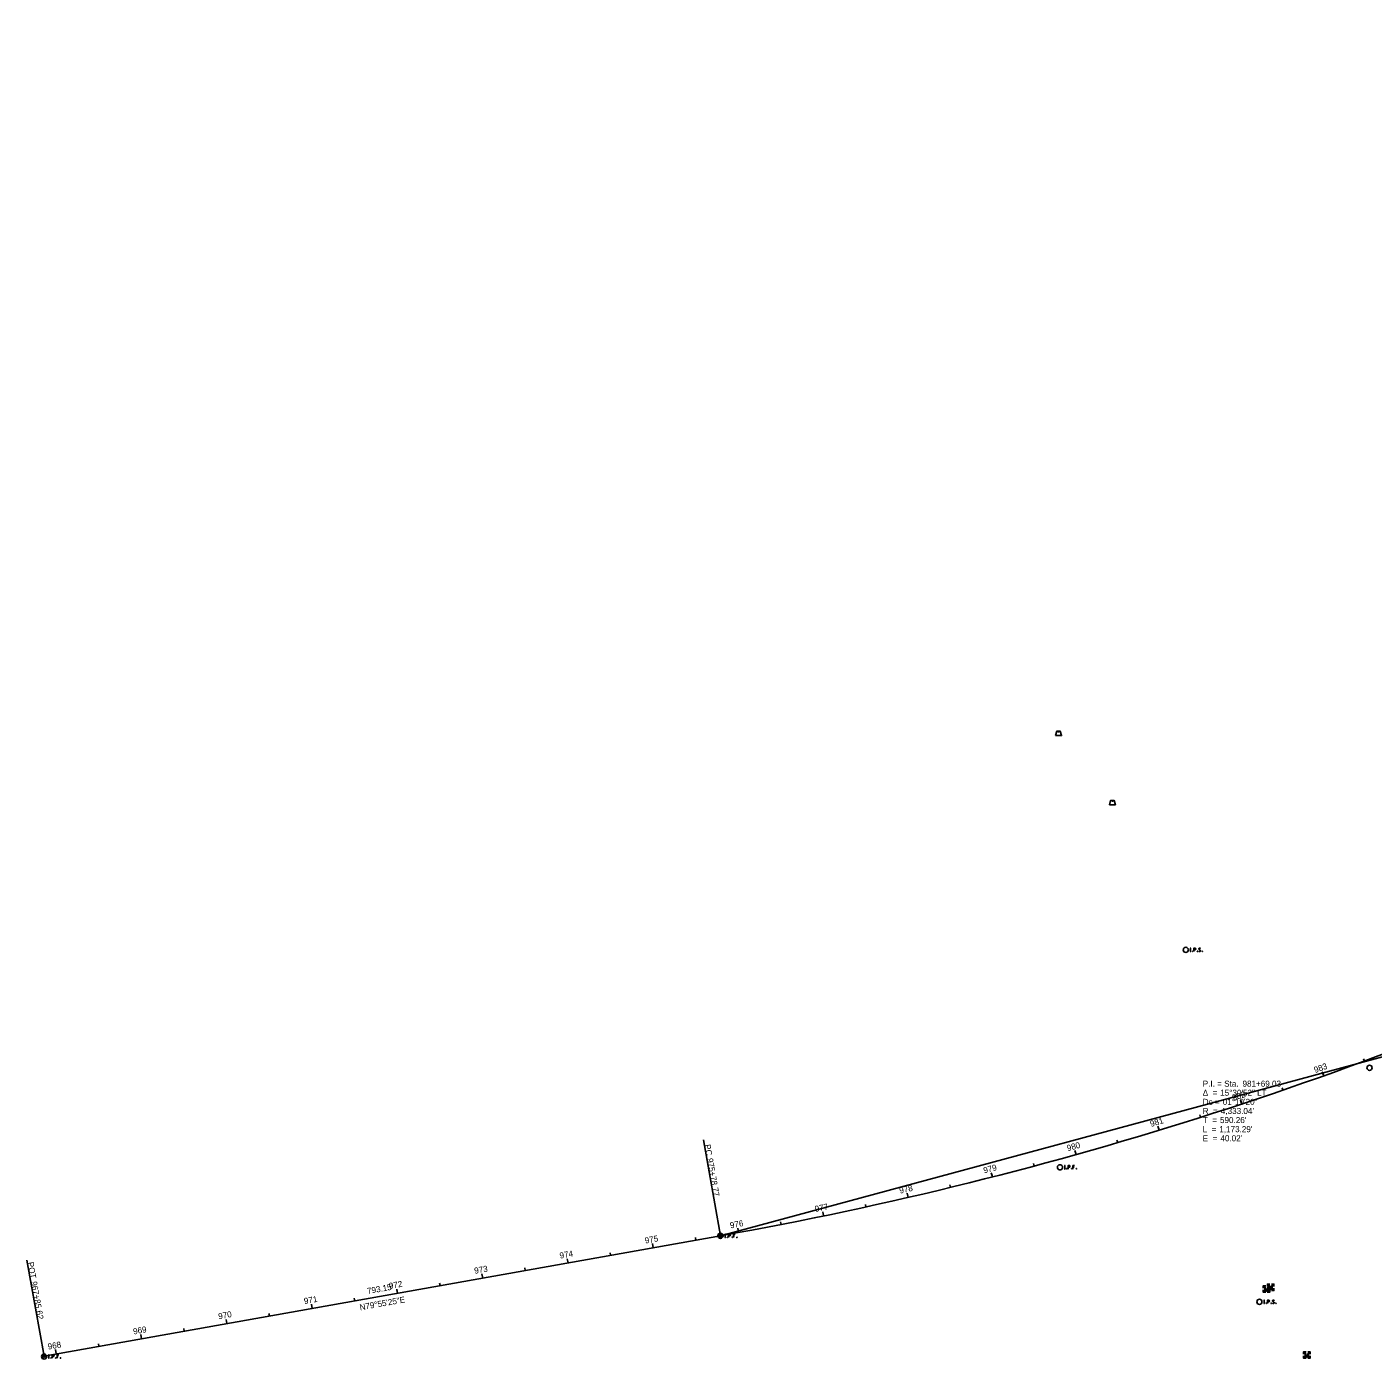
# Model space of a CAD drawing. Extents: x 2192033 to 2198234, y 657975 to 662607.
# Drawn here: x 2192033 to 2193587, y 660215 to 661753 of the extents above; entities that cross this region are included whole.
import ezdxf

# ---------------------------------------------------------------- set-up
doc = ezdxf.new("R2010")
doc.units = 0
for name, color, linetype in [('BR_P_Gen_Approach_Slab', 7, 'Continuous'), ('GE_X_Alignment_1000_Curve_Data', 7, 'Continuous'), ('GE_X_Alignment_1000_Stations', 7, 'Continuous'), ('GE_X_Alignment_100_Curve_Data', 7, 'Continuous'), ('GE_X_Alignment_100_Stations', 7, 'Continuous'), ('GE_X_Alignment_500_Curve_Data', 7, 'Continuous'), ('GE_X_Alignment_500_Stations', 7, 'Continuous'), ('RD_P_Text', 7, 'Continuous'), ('SH_Border', 7, 'Continuous'), ('SH_Named_Boundary', 7, 'Continuous')]:
    doc.layers.add(name, color=color, linetype=linetype)

msp = doc.modelspace()

# ---------------------------------------------------------------- linework, layer by layer
at = {"layer": 'BR_P_Gen_Approach_Slab'}
for points in [[(2193375.5, 660689.6), (2193376.4, 660689.6)], [(2193375.5, 660685.6), (2193376.4, 660685.6)], [(2193376, 660685.6), (2193376, 660689.6)], [(2193378.4, 660686.2), (2193378.5, 660686.2), (2193378.6, 660686.1), (2193378.7, 660686), (2193378.7, 660685.8), (2193378.6, 660685.7), (2193378.5, 660685.6), (2193378.4, 660685.6), (2193378.3, 660685.7), (2193378.2, 660685.8), (2193378.2, 660686), (2193378.3, 660686.1), (2193378.4, 660686.2)], [(2193379.9, 660685.6), (2193379.9, 660689.6), (2193381.2, 660689.6), (2193381.4, 660689.6), (2193381.6, 660689.5), (2193381.6, 660689.5), (2193381.7, 660689.4), (2193381.8, 660689.3), (2193381.9, 660689.1), (2193382, 660688.9), (2193382, 660688.5), (2193381.9, 660688.3), (2193381.9, 660688.2), (2193381.8, 660687.9), (2193381.7, 660687.8), (2193381.6, 660687.8), (2193381.4, 660687.7), (2193381.2, 660687.7), (2193379.9, 660687.7)], [(2193384, 660686.2), (2193384.1, 660686.2), (2193384.2, 660686.1), (2193384.3, 660686), (2193384.3, 660685.8), (2193384.2, 660685.7), (2193384.1, 660685.6), (2193384, 660685.6), (2193383.9, 660685.7), (2193383.8, 660685.8), (2193383.8, 660686), (2193383.9, 660686.1), (2193384, 660686.2)], [(2193387.4, 660689.4), (2193387.4, 660689.4), (2193387.3, 660689.5), (2193387, 660689.6), (2193386.7, 660689.6), (2193386.5, 660689.6), (2193386.4, 660689.6), (2193386.1, 660689.5), (2193385.8, 660689.4), (2193385.6, 660689.1), (2193385.5, 660688.9), (2193385.5, 660688.7), (2193385.6, 660688.4), (2193385.8, 660688.2), (2193387.3, 660687.2), (2193387.5, 660687.1), (2193387.5, 660687), (2193387.6, 660686.8), (2193387.6, 660686.6), (2193387.5, 660686.4), (2193387.5, 660686.3), (2193387.5, 660686.1), (2193387.4, 660686), (2193387.3, 660685.9), (2193387.3, 660685.8), (2193387.2, 660685.8), (2193387.1, 660685.7), (2193387, 660685.7), (2193386.7, 660685.6), (2193386.3, 660685.6), (2193386.1, 660685.7), (2193385.7, 660685.9), (2193385.5, 660686.1)], [(2193389.5, 660686.2), (2193389.6, 660686.2), (2193389.7, 660686.1), (2193389.8, 660686), (2193389.8, 660685.8), (2193389.7, 660685.7), (2193389.6, 660685.6), (2193389.5, 660685.6), (2193389.4, 660685.7), (2193389.3, 660685.8), (2193389.3, 660686), (2193389.4, 660686.1), (2193389.5, 660686.2)], [(2193460.6, 660283.4), (2193461.5, 660283.4)], [(2193460.6, 660279.4), (2193461.5, 660279.4)], [(2193461, 660279.4), (2193461, 660283.4)], [(2193463.4, 660279.9), (2193463.5, 660279.9), (2193463.6, 660279.9), (2193463.7, 660279.7), (2193463.7, 660279.6), (2193463.6, 660279.5), (2193463.5, 660279.4), (2193463.4, 660279.4), (2193463.3, 660279.5), (2193463.2, 660279.6), (2193463.2, 660279.7), (2193463.3, 660279.9), (2193463.4, 660279.9)], [(2193464.9, 660279.4), (2193464.9, 660283.4), (2193466.2, 660283.4), (2193466.4, 660283.4), (2193466.6, 660283.3), (2193466.7, 660283.2), (2193466.7, 660283.2), (2193466.9, 660283), (2193466.9, 660282.9), (2193467, 660282.6), (2193467, 660282.2), (2193467, 660282.1), (2193466.9, 660281.9), (2193466.8, 660281.7), (2193466.7, 660281.6), (2193466.6, 660281.5), (2193466.5, 660281.5), (2193466.2, 660281.4), (2193464.9, 660281.4)], [(2193469, 660279.9), (2193469.2, 660279.9), (2193469.3, 660279.9), (2193469.3, 660279.7), (2193469.3, 660279.6), (2193469.3, 660279.5), (2193469.2, 660279.4), (2193469, 660279.4), (2193468.9, 660279.5), (2193468.9, 660279.6), (2193468.9, 660279.7), (2193468.9, 660279.9), (2193469, 660279.9)], [(2193472.4, 660283.1), (2193472.4, 660283.2), (2193472.3, 660283.2), (2193472.1, 660283.3), (2193471.8, 660283.4), (2193471.5, 660283.4), (2193471.5, 660283.4), (2193471.1, 660283.3), (2193470.8, 660283.1), (2193470.6, 660282.9), (2193470.5, 660282.6), (2193470.5, 660282.4), (2193470.6, 660282.2), (2193470.8, 660282), (2193472.3, 660281), (2193472.5, 660280.9), (2193472.5, 660280.8), (2193472.6, 660280.6), (2193472.6, 660280.4), (2193472.6, 660280.2), (2193472.5, 660280.1), (2193472.5, 660279.9), (2193472.4, 660279.8), (2193472.4, 660279.7), (2193472.3, 660279.6), (2193472.2, 660279.5), (2193472.1, 660279.5), (2193472, 660279.4), (2193471.8, 660279.4), (2193471.4, 660279.4), (2193471.1, 660279.5), (2193470.8, 660279.7), (2193470.5, 660279.9)], [(2193474.5, 660279.9), (2193474.6, 660279.9), (2193474.7, 660279.9), (2193474.8, 660279.7), (2193474.8, 660279.6), (2193474.7, 660279.5), (2193474.6, 660279.4), (2193474.5, 660279.4), (2193474.4, 660279.5), (2193474.3, 660279.6), (2193474.3, 660279.7), (2193474.4, 660279.9), (2193474.5, 660279.9)]]:
    msp.add_lwpolyline(points, dxfattribs=at)
for centre in [(2193370.5, 660687.6), (2193455.5, 660281.4)]:
    msp.add_circle(centre, 3, dxfattribs=at)
at = {"layer": 'GE_X_Alignment_1000_Stations'}
for p, q in [((2192833.4, 660357.6), (2192813.7, 660468.4)), ((2193243.9, 660451.3), (2193242.5, 660456.1)), ((2192755.8, 660343.8), (2192755.3, 660346.8)), ((2192052.5, 660218.8), (2192032.8, 660329.6)), ((2192263.5, 660256.3), (2192262.7, 660261.2))]:
    msp.add_line(p, q, dxfattribs=at)
for centre in [(2192833.4, 660357.6), (2192052.5, 660218.8)]:
    msp.add_circle(centre, 1.5, dxfattribs=at)
at = {"layer": 'GE_X_Alignment_100_Stations'}
for p, q in [((2193576.7, 660559.2), (2193575.7, 660562)), ((2193529.7, 660542.2), (2193528, 660546.9)), ((2193482.5, 660525.6), (2193481.6, 660528.5)), ((2193435.1, 660509.7), (2193433.6, 660514.4)), ((2193387.6, 660494.3), (2193386.7, 660497.1)), ((2193339.8, 660479.4), (2193338.4, 660484.2)), ((2192833.4, 660357.6), (2192813.7, 660468.4)), ((2193291.9, 660465.1), (2193291.1, 660468)), ((2193243.9, 660451.3), (2193242.5, 660456.1)), ((2193195.6, 660438.1), (2193194.9, 660441)), ((2193098.8, 660413.4), (2193098.1, 660416.3)), ((2193147.3, 660425.5), (2193146, 660430.3)), ((2193050.1, 660401.8), (2193049, 660406.7)), ((2192952.4, 660380.5), (2192951.4, 660385.4)), ((2193001.3, 660390.9), (2193000.7, 660393.8)), ((2192903.4, 660370.6), (2192902.8, 660373.6)), ((2192805, 660352.6), (2192804.5, 660355.5)), ((2192854.3, 660361.4), (2192853.4, 660366.3)), ((2192706.6, 660335.1), (2192706.1, 660338)), ((2192755.8, 660343.8), (2192754.9, 660348.7)), ((2192052.5, 660218.8), (2192032.8, 660329.6)), ((2192657.4, 660326.3), (2192656.5, 660331.2)), ((2192558.9, 660308.8), (2192558, 660313.7)), ((2192608.1, 660317.6), (2192607.6, 660320.5)), ((2192460.4, 660291.3), (2192459.6, 660296.2)), ((2192509.7, 660300.1), (2192509.1, 660303)), ((2192362, 660273.8), (2192361.1, 660278.7)), ((2192411.2, 660282.6), (2192410.7, 660285.5)), ((2192263.5, 660256.3), (2192262.7, 660261.2)), ((2192312.8, 660265.1), (2192312.2, 660268)), ((2192214.3, 660247.6), (2192213.8, 660250.5)), ((2192115.8, 660230.1), (2192115.3, 660233)), ((2192165.1, 660238.8), (2192164.2, 660243.8)), ((2192066.6, 660221.3), (2192065.7, 660226.3))]:
    msp.add_line(p, q, dxfattribs=at)
for centre in [(2192833.4, 660357.6), (2192052.5, 660218.8)]:
    msp.add_circle(centre, 1.5, dxfattribs=at)
at = {"layer": 'GE_X_Alignment_500_Stations'}
for p, q in [((2193529.7, 660542.2), (2193528.7, 660545)), ((2193435.1, 660509.7), (2193434.2, 660512.5)), ((2193339.8, 660479.4), (2193339, 660482.3)), ((2192833.4, 660357.6), (2192813.7, 660468.4)), ((2193243.9, 660451.3), (2193242.5, 660456.1)), ((2193147.3, 660425.5), (2193146.5, 660428.4)), ((2193050.1, 660401.8), (2193049.4, 660404.8)), ((2192952.4, 660380.5), (2192951.8, 660383.4)), ((2192854.3, 660361.4), (2192853.7, 660364.3)), ((2192755.8, 660343.8), (2192754.9, 660348.7)), ((2192052.5, 660218.8), (2192032.8, 660329.6)), ((2192657.4, 660326.3), (2192656.8, 660329.3)), ((2192558.9, 660308.8), (2192558.4, 660311.8)), ((2192460.4, 660291.3), (2192459.9, 660294.3)), ((2192362, 660273.8), (2192361.5, 660276.8)), ((2192263.5, 660256.3), (2192262.7, 660261.2)), ((2192165.1, 660238.8), (2192164.5, 660241.8)), ((2192066.6, 660221.3), (2192066.1, 660224.3))]:
    msp.add_line(p, q, dxfattribs=at)
for centre in [(2192833.4, 660357.6), (2192052.5, 660218.8)]:
    msp.add_circle(centre, 1.5, dxfattribs=at)
at = {"layer": 'RD_P_Text'}
msp.add_line((2192052.5, 660218.8), (2192833.4, 660357.6), dxfattribs=at)
msp.add_arc((2192075.3, 664623.8), 4333, 280.0763, 295.5908, dxfattribs=at)
at = {"layer": 'SH_Border'}
msp.add_line((2192833.4, 660357.6), (2197996.1, 661752.8), dxfattribs=at)
at = {"layer": 'SH_Named_Boundary'}
for p, q in [((2193223.6, 660940), (2193223.6, 660938.5)), ((2193285.8, 660860.1), (2193285.8, 660858.6)), ((2193463.7, 660296.2), (2193463.7, 660296.2)), ((2193468.5, 660298), (2193468.5, 660298)), ((2193510.4, 660219.9), (2193510.4, 660219.9))]:
    msp.add_line(p, q, dxfattribs=at)
for points in [[(2193220, 660935), (2193227.1, 660935), (2193225.6, 660940), (2193221.5, 660940)], [(2193282.3, 660855.1), (2193289.3, 660855.1), (2193287.8, 660860.1), (2193283.8, 660860.1)]]:
    msp.add_lwpolyline(points, close=True, dxfattribs=at)
for points in [[(2193230.4, 660438.7), (2193231.3, 660438.7)], [(2193230.4, 660434.7), (2193231.3, 660434.7)], [(2193230.8, 660434.7), (2193230.8, 660438.7)], [(2193233.2, 660435.3), (2193233.3, 660435.3), (2193233.4, 660435.2), (2193233.5, 660435.1), (2193233.5, 660434.9), (2193233.4, 660434.8), (2193233.3, 660434.7), (2193233.2, 660434.7), (2193233.1, 660434.8), (2193233, 660434.9), (2193233, 660435.1), (2193233.1, 660435.2), (2193233.2, 660435.3)], [(2193234.7, 660434.7), (2193234.7, 660438.7), (2193236, 660438.7), (2193236.2, 660438.7), (2193236.4, 660438.6), (2193236.5, 660438.6), (2193236.5, 660438.5), (2193236.7, 660438.4), (2193236.7, 660438.2), (2193236.8, 660438), (2193236.8, 660437.6), (2193236.8, 660437.4), (2193236.7, 660437.3), (2193236.6, 660437), (2193236.5, 660436.9), (2193236.4, 660436.9), (2193236.3, 660436.8), (2193236, 660436.8), (2193234.7, 660436.8)], [(2193238.8, 660435.3), (2193239, 660435.3), (2193239.1, 660435.2), (2193239.1, 660435.1), (2193239.1, 660434.9), (2193239.1, 660434.8), (2193239, 660434.7), (2193238.8, 660434.7), (2193238.7, 660434.8), (2193238.7, 660434.9), (2193238.7, 660435.1), (2193238.7, 660435.2), (2193238.8, 660435.3)], [(2193242.2, 660438.7), (2193240.3, 660438.7), (2193240.3, 660434.7)], [(2193240.3, 660436.8), (2193241.7, 660436.8)], [(2193244.2, 660435.3), (2193244.3, 660435.3), (2193244.4, 660435.2), (2193244.5, 660435.1), (2193244.5, 660434.9), (2193244.4, 660434.8), (2193244.3, 660434.7), (2193244.2, 660434.7), (2193244.1, 660434.8), (2193244, 660434.9), (2193244, 660435.1), (2193244.1, 660435.2), (2193244.2, 660435.3)], [(2192838.4, 660359.6), (2192839.3, 660359.6)], [(2192838.4, 660355.6), (2192839.3, 660355.6)], [(2192838.8, 660355.6), (2192838.8, 660359.6)], [(2192841.2, 660356.1), (2192841.4, 660356.1), (2192841.5, 660356.1), (2192841.6, 660355.9), (2192841.6, 660355.8), (2192841.5, 660355.7), (2192841.4, 660355.6), (2192841.2, 660355.6), (2192841.2, 660355.7), (2192841.1, 660355.8), (2192841.1, 660355.9), (2192841.2, 660356.1), (2192841.2, 660356.1)], [(2192842.8, 660355.6), (2192842.8, 660359.6), (2192844.1, 660359.6), (2192844.2, 660359.6), (2192844.4, 660359.5), (2192844.5, 660359.4), (2192844.6, 660359.4), (2192844.7, 660359.2), (2192844.8, 660359.1), (2192844.8, 660358.8), (2192844.8, 660358.4), (2192844.8, 660358.3), (2192844.7, 660358.1), (2192844.6, 660357.9), (2192844.5, 660357.8), (2192844.4, 660357.7), (2192844.3, 660357.7), (2192844.1, 660357.6), (2192842.8, 660357.6)], [(2192846.9, 660356.1), (2192847, 660356.1), (2192847.1, 660356.1), (2192847.2, 660355.9), (2192847.2, 660355.8), (2192847.1, 660355.7), (2192847, 660355.6), (2192846.9, 660355.6), (2192846.8, 660355.7), (2192846.7, 660355.8), (2192846.7, 660355.9), (2192846.8, 660356.1), (2192846.9, 660356.1)], [(2192850.3, 660359.6), (2192848.4, 660359.6), (2192848.4, 660355.6)], [(2192848.4, 660357.6), (2192849.7, 660357.6)], [(2192852.2, 660356.1), (2192852.4, 660356.1), (2192852.5, 660356.1), (2192852.5, 660355.9), (2192852.5, 660355.8), (2192852.5, 660355.7), (2192852.4, 660355.6), (2192852.2, 660355.6), (2192852.2, 660355.7), (2192852.1, 660355.8), (2192852.1, 660355.9), (2192852.2, 660356.1), (2192852.2, 660356.1)], [(2193459.9, 660297.1), (2193459.9, 660300), (2193462.8, 660300)], [(2193462.8, 660292.4), (2193459.9, 660292.4), (2193459.9, 660295.3)], [(2193461.8, 660293.7), (2193461.8, 660298.7), (2193463.7, 660293.7), (2193465.5, 660298.7), (2193465.5, 660293.7)], [(2193464.6, 660300), (2193467.5, 660300), (2193467.5, 660297.1)], [(2193467.5, 660295.3), (2193467.5, 660292.4), (2193464.6, 660292.4)], [(2193464.8, 660299), (2193464.8, 660301.8), (2193467.6, 660301.8)], [(2193467.6, 660294.3), (2193464.8, 660294.3), (2193464.8, 660297.1)], [(2193466.7, 660295.5), (2193466.7, 660300.5), (2193468.5, 660295.5), (2193470.4, 660300.5), (2193470.4, 660295.5)], [(2193469.4, 660301.8), (2193472.3, 660301.8), (2193472.3, 660299)], [(2193472.3, 660297.1), (2193472.3, 660294.3), (2193469.4, 660294.3)], [(2192057.6, 660220.3), (2192058.5, 660220.3)], [(2192057.6, 660216.3), (2192058.5, 660216.3)], [(2192058.1, 660216.3), (2192058.1, 660220.3)], [(2192060.5, 660216.9), (2192060.6, 660216.9), (2192060.7, 660216.8), (2192060.8, 660216.7), (2192060.8, 660216.5), (2192060.7, 660216.4), (2192060.6, 660216.3), (2192060.5, 660216.3), (2192060.4, 660216.4), (2192060.3, 660216.5), (2192060.3, 660216.7), (2192060.4, 660216.8), (2192060.5, 660216.9)], [(2192062, 660216.3), (2192062, 660220.3), (2192063.3, 660220.3), (2192063.5, 660220.3), (2192063.6, 660220.2), (2192063.7, 660220.2), (2192063.8, 660220.1), (2192063.9, 660220), (2192064, 660219.8), (2192064.1, 660219.6), (2192064.1, 660219.2), (2192064, 660219), (2192064, 660218.9), (2192063.9, 660218.6), (2192063.8, 660218.5), (2192063.7, 660218.5), (2192063.5, 660218.4), (2192063.3, 660218.4), (2192062, 660218.4)], [(2192066.1, 660216.9), (2192066.2, 660216.9), (2192066.3, 660216.8), (2192066.4, 660216.7), (2192066.4, 660216.5), (2192066.3, 660216.4), (2192066.2, 660216.3), (2192066.1, 660216.3), (2192066, 660216.4), (2192065.9, 660216.5), (2192065.9, 660216.7), (2192066, 660216.8), (2192066.1, 660216.9)], [(2192069.5, 660220.3), (2192067.6, 660220.3), (2192067.6, 660216.3)], [(2192067.6, 660218.4), (2192069, 660218.4)], [(2192071.5, 660216.9), (2192071.6, 660216.9), (2192071.7, 660216.8), (2192071.8, 660216.7), (2192071.8, 660216.5), (2192071.7, 660216.4), (2192071.6, 660216.3), (2192071.5, 660216.3), (2192071.4, 660216.4), (2192071.3, 660216.5), (2192071.3, 660216.7), (2192071.4, 660216.8), (2192071.5, 660216.9)], [(2193506.6, 660220.9), (2193506.6, 660223.7), (2193509.4, 660223.7)], [(2193509.4, 660216.2), (2193506.6, 660216.2), (2193506.6, 660219)], [(2193508.5, 660217.4), (2193508.5, 660222.4), (2193510.4, 660217.4), (2193512.2, 660222.4), (2193512.2, 660217.4)], [(2193511.3, 660223.7), (2193514.1, 660223.7), (2193514.1, 660220.9)], [(2193514.1, 660219), (2193514.1, 660216.2), (2193511.3, 660216.2)]]:
    msp.add_lwpolyline(points, dxfattribs=at)
for centre in [(2193582.7, 660551.5), (2193225.3, 660436.7), (2192833.4, 660357.6), (2192052.6, 660218.3)]:
    msp.add_circle(centre, 3, dxfattribs=at)

# ---------------------------------------------------------------- texts
at = {"layer": 'GE_X_Alignment_1000_Curve_Data'}
for s, p in [('Δ  = ', (2193390.1, 660519.2)), ('P.I. = Sta. ', (2193390.1, 660529.7)), ('15°30\'52" LT', (2193410.2, 660519.2)), ('981+69.03', (2193436, 660529.7)), ('Dc = ', (2193390.1, 660508.7)), ('01°19\'20"', (2193413.2, 660508.7)), ('T  = ', (2193390.1, 660487.7)), ('R  = ', (2193390.1, 660498.2)), ("590.26'", (2193410, 660487.7)), ("4,333.04'", (2193411, 660498.2)), ('L  = ', (2193390.1, 660477.2)), ("1,173.29'", (2193409.2, 660477.2)), ('E  = ', (2193390.1, 660466.7)), ("40.02'", (2193410.5, 660466.7))]:
    msp.add_text(s, height=7, dxfattribs=at).set_placement(p)
at = {"layer": 'GE_X_Alignment_1000_Stations'}
for s, rotation, p in [('PC', 280.0763, (2192814.8, 660462.5)), ('980', 15.6462, (2193234.3, 660455.2)), ('975+78.77', 280.0763, (2192817.7, 660446.5)), ('POT', 280.0763, (2192033.4, 660326.8)), ('967+85.62', 280.0763, (2192037.4, 660304.4)), ("793.15'", 10.0763, (2192426.1, 660290.3)), ('N79°55\'25"E', 10.0763, (2192417.5, 660271.5)), ('970', 10.0763, (2192254.3, 660261.2))]:
    msp.add_text(s, height=7, rotation=rotation, dxfattribs=at).set_placement(p)
at = {"layer": 'GE_X_Alignment_100_Curve_Data'}
for s, p in [('Δ  = ', (2193390.1, 660519.2)), ('P.I. = Sta. ', (2193390.1, 660529.7)), ('15°30\'52" LT', (2193410.2, 660519.2)), ('981+69.03', (2193436, 660529.7)), ('Dc = ', (2193390.1, 660508.7)), ('01°19\'20"', (2193413.2, 660508.7)), ('T  = ', (2193390.1, 660487.7)), ('R  = ', (2193390.1, 660498.2)), ("590.26'", (2193410, 660487.7)), ("4,333.04'", (2193411, 660498.2)), ('L  = ', (2193390.1, 660477.2)), ("1,173.29'", (2193409.2, 660477.2)), ('E  = ', (2193390.1, 660466.7)), ("40.02'", (2193410.5, 660466.7))]:
    msp.add_text(s, height=7, dxfattribs=at).set_placement(p)
at = {"layer": 'GE_X_Alignment_100_Stations'}
for s, rotation, p in [('983', 19.6131, (2193519.9, 660545.4)), ('982', 18.2908, (2193425.4, 660513.2)), ('981', 16.9685, (2193330.5, 660483.2)), ('PC', 280.0763, (2192814.8, 660462.5)), ('980', 15.6462, (2193234.3, 660455.2)), ('975+78.77', 280.0763, (2192817.7, 660446.5)), ('979', 14.3239, (2193137.8, 660429.6)), ('978', 13.0016, (2193040.7, 660406.2)), ('977', 11.6793, (2192943, 660385)), ('976', 10.357, (2192845, 660366.1)), ('975', 10.0763, (2192746.6, 660348.6)), ('974', 10.0763, (2192648.3, 660331.2)), ('POT', 280.0763, (2192033.4, 660326.8)), ('973', 10.0763, (2192549.8, 660313.7)), ('967+85.62', 280.0763, (2192037.4, 660304.4)), ('972', 10.0763, (2192451.3, 660296.2)), ('971', 10.0763, (2192353.2, 660278.7)), ('N79°55\'25"E', 10.0763, (2192417.5, 660271.5)), ('970', 10.0763, (2192254.3, 660261.2)), ('969', 10.0763, (2192156, 660243.7)), ('968', 10.0763, (2192057.4, 660226.2))]:
    msp.add_text(s, height=7, rotation=rotation, dxfattribs=at).set_placement(p)
at = {"layer": 'GE_X_Alignment_500_Curve_Data'}
for s, p in [('Δ  = ', (2193390.1, 660519.2)), ('P.I. = Sta. ', (2193390.1, 660529.7)), ('15°30\'52" LT', (2193410.2, 660519.2)), ('981+69.03', (2193436, 660529.7)), ('Dc = ', (2193390.1, 660508.7)), ('01°19\'20"', (2193413.2, 660508.7)), ('T  = ', (2193390.1, 660487.7)), ('R  = ', (2193390.1, 660498.2)), ("590.26'", (2193410, 660487.7)), ("4,333.04'", (2193411, 660498.2)), ('L  = ', (2193390.1, 660477.2)), ("1,173.29'", (2193409.2, 660477.2)), ('E  = ', (2193390.1, 660466.7)), ("40.02'", (2193410.5, 660466.7))]:
    msp.add_text(s, height=7, dxfattribs=at).set_placement(p)
at = {"layer": 'GE_X_Alignment_500_Stations'}
for s, rotation, p in [('PC', 280.0763, (2192814.8, 660462.5)), ('980', 15.6462, (2193234.3, 660455.2)), ('975+78.77', 280.0763, (2192817.7, 660446.5)), ('975', 10.0763, (2192746.6, 660348.6)), ('POT', 280.0763, (2192033.4, 660326.8)), ('967+85.62', 280.0763, (2192037.4, 660304.4)), ("793.15'", 10.0763, (2192426.1, 660290.3)), ('N79°55\'25"E', 10.0763, (2192417.5, 660271.5)), ('970', 10.0763, (2192254.3, 660261.2))]:
    msp.add_text(s, height=7, rotation=rotation, dxfattribs=at).set_placement(p)

doc.saveas('drawing.dxf')
